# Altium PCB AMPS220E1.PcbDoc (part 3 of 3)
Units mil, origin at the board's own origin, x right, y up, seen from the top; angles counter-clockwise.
Board outline 4800 x 2800 mil, 4 copper layers (Top Layer, GND_Split, GROUND, Bottom Layer), stack 62.6 mil thick; 263 components, 127 nets, 663 pads, 225 vias.
Unrouted connection lines stored in the file: 38.
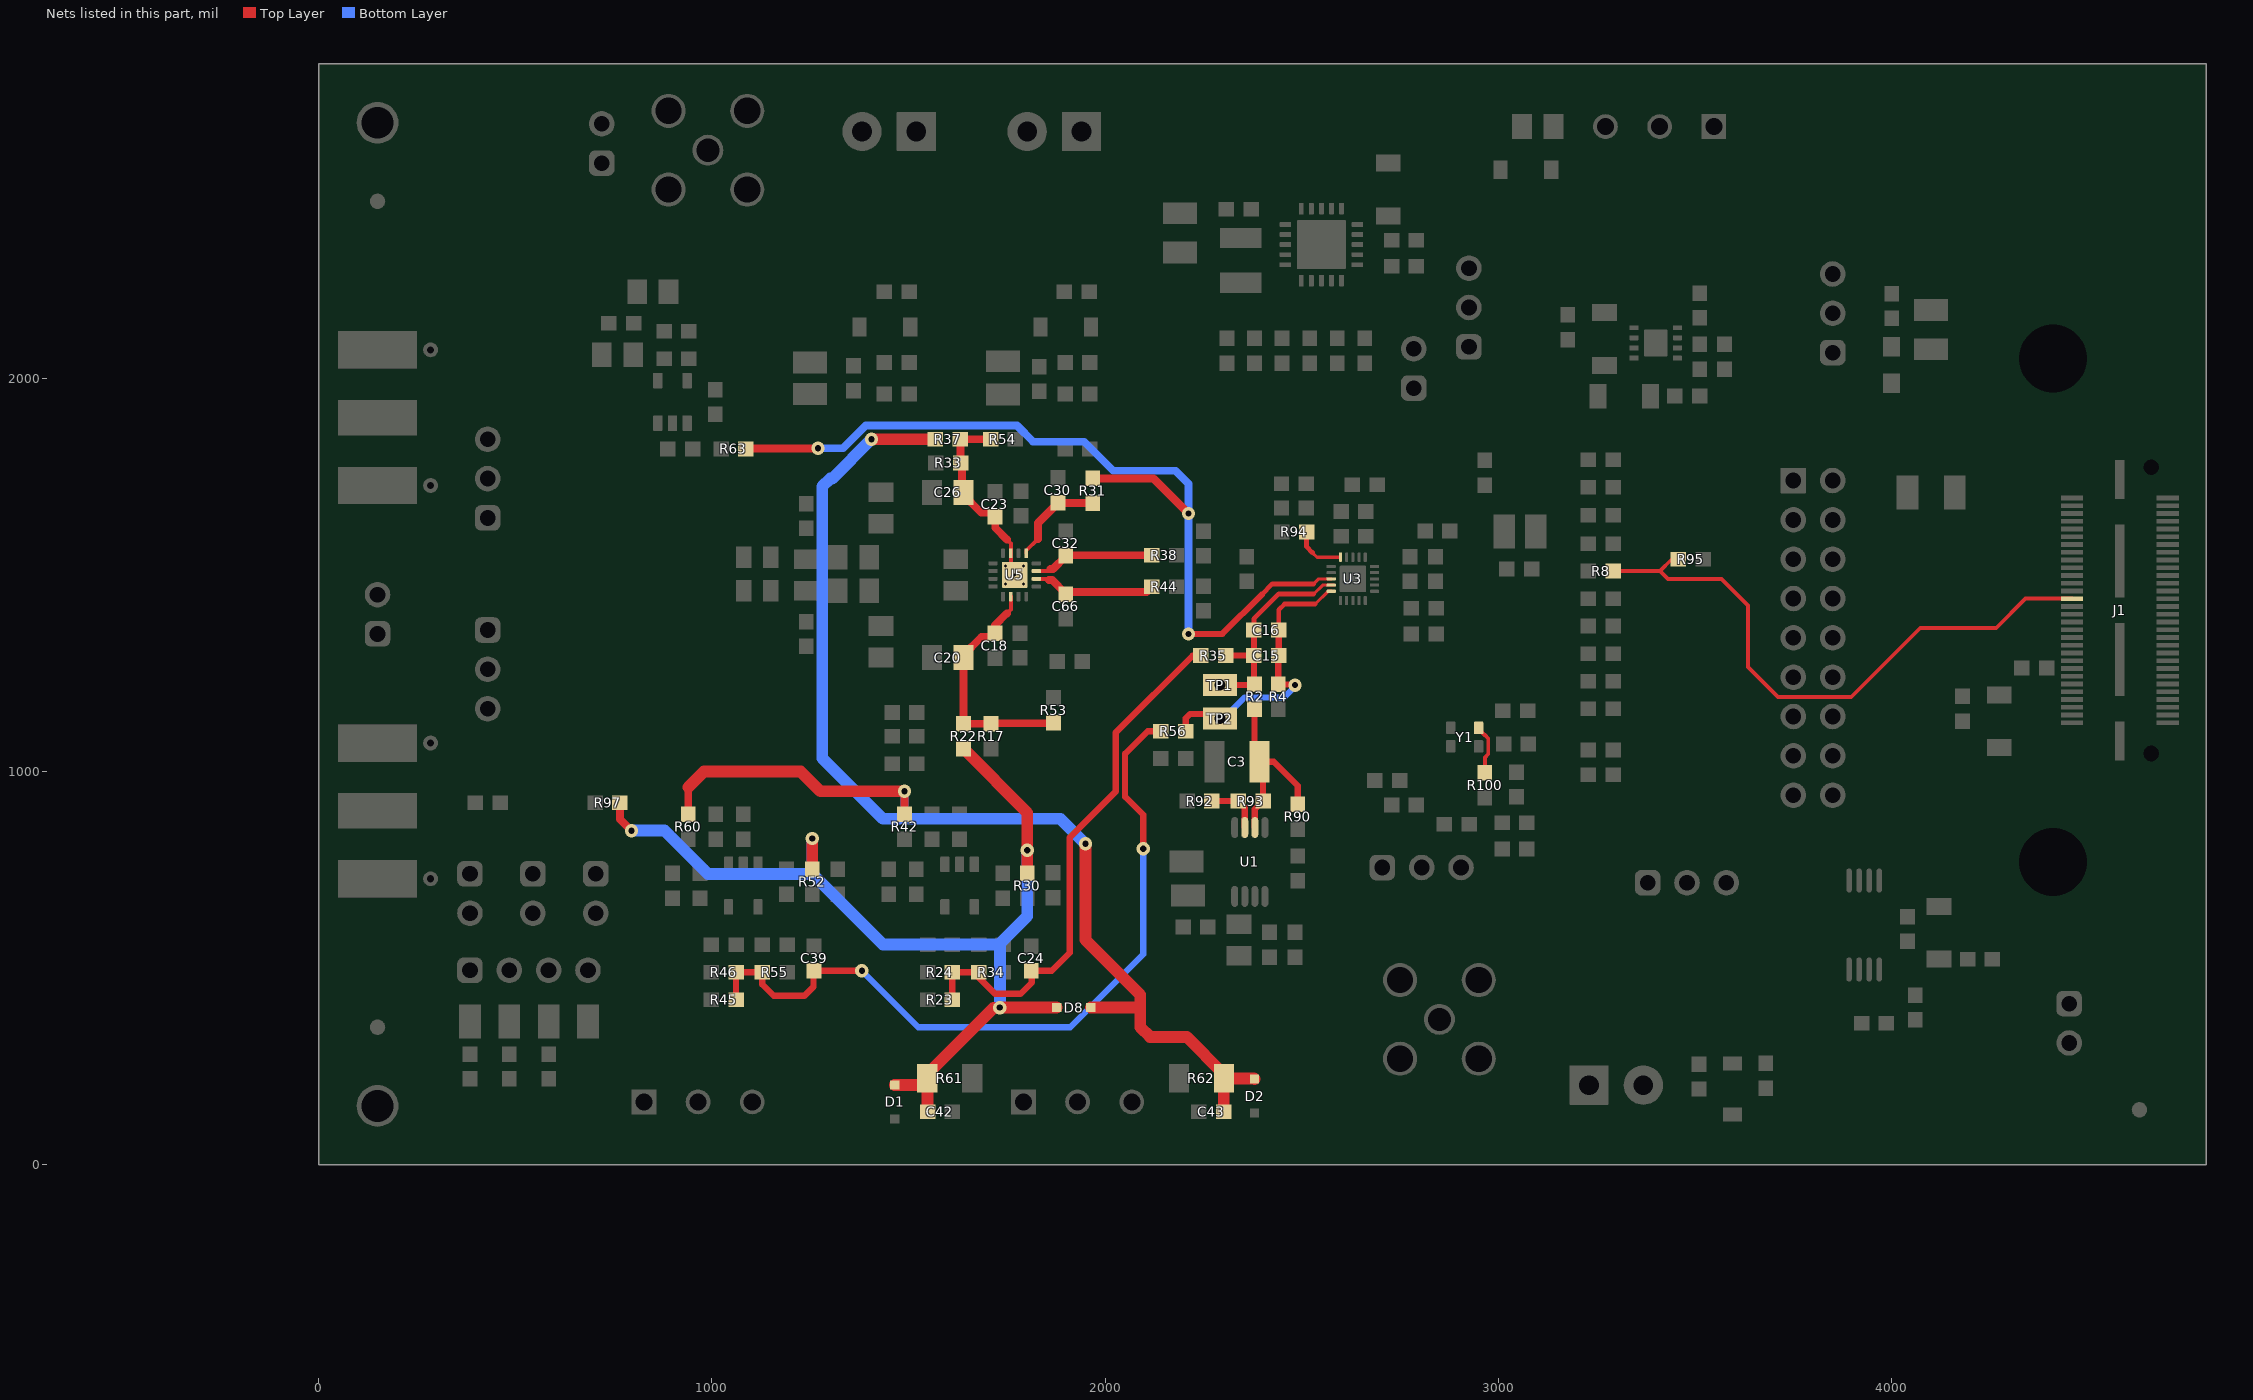
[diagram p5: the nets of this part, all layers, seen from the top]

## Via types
v1: diameter 34, hole 16, Top Layer to Bottom Layer, tented both sides, 161 vias
v2: diameter 34, hole 16, Top Layer to Bottom Layer, 30 vias
v3: diameter 50, hole 28, Top Layer to Bottom Layer, 15 vias
v4: diameter 19.68, hole 7.87, Top Layer to Bottom Layer, tented both sides, 10 vias
v5: diameter 19.68, hole 7.87, Top Layer to Bottom Layer, 9 vias

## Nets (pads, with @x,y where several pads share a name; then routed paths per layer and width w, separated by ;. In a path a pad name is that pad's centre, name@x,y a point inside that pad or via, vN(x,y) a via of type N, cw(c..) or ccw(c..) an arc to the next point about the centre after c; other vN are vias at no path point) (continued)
NetR92_2: R92.2 R93.1 U1.7 | length 141.1
  Top Layer w16: R92.2@2271.5,925 R93.1@2338.5,924.98 2355.16,908.33 U1.7@2355.16,857.84
NetR94_2: R94.2 U3.20 | length 135
  Top Layer w8: 2527.05,1556.92 2538.7,1545.27 2538.7,1545.12 U3.20@2598.5,1545.12
  Top Layer w12: R94.2@2512.16,1609.33 2512.16,1571.81 2527.05,1556.92
NetR100_2: R100.2 Y1.3 | length 128.7
  Top Layer w10: Y1.3@2949.71,1111.31 2949.71,1107.37 2964.57,1092.51 2965.61,1092.51 2974.22,1083.9 2974.22,1044.23 2965.65,1035.66 R100.2@2965.65,996.89
OUTN: C32.1 R38.1 U5.11 | length 310.6
  Top Layer w10: U5.11@1825.12,1509.84 1856.13,1509.84 1861.21,1514.92
  Top Layer w20: 1861.21,1514.92 1867.4,1514.92 1900,1547.52 C32.1@1900,1548.5 1901.5,1550 R38.1@2118.5,1550
OUTP: C66.1 R44.1 U5.10 | length 316.3
  Top Layer w10: U5.10@1825.12,1490.16 1857.65,1490.16
  Top Layer w20: 1857.65,1486.97 1865.51,1486.97 1900,1452.48 C66.1@1900,1451.5 1905,1456.5 2105,1456.5 R44.1@2118.5,1470
REFN: C15.1 C16.2 R4.2 R56.2 TP2.1 U3.5 | length 773.1
  Top Layer w8: 2513.86,1426.02 2534.65,1426.02 2567.13,1458.5 U3.5@2574.88,1458.5
  Top Layer w12: C15.1@2440,1288.5 C15.1@2441.5,1295 ; C16.2@2441.5,1360 2441.5,1411.4 2456.12,1426.02 2534.65,1426.02
  Top Layer w16: R56.2@2205.04,1102.43 2205.04,1135.38 2216.31,1146.65 2280.1,1146.65 v3(2291.74,1135) TP2.1@2286.04,1129.3 ; C15.1@2440,1288.5 R4.2@2440,1221.5 2481.46,1221.5 v1(2482.95,1220) ; C15.1@2441.5,1295 C16.2@2441.5,1360
  Bottom Layer w16: v3(2291.74,1135) 2301.44,1135 2355,1188.56 2454.16,1188.56 2454.46,1188.25 2482.95,1216.74 v1(2482.95,1220)
REFNb: C39.1 R45.1 R46.1 R55.2 R56.1 | length 1977.8
  Top Layer w16: R45.1@1061.5,420 R46.1@1061.5,490 R55.2@1128.5,490 1128.5,458.86 1157.36,430 1235.59,430 1258.5,452.91 1258.5,492.01 C39.1@1260,493.5 v1(1381.65,493.5) ; v1(2097.05,803.5) 2097.05,890.04 2050.74,936.35 2050.74,1045.12 2108.05,1102.43 R56.1@2142.05,1102.43
  Bottom Layer w16: v1(1381.65,493.5) 1525.16,350 1911.33,350 2097.05,535.72 v1(2097.05,803.5)
REFP: C15.2 C16.1 R2.2 R35.2 TP1.1 U3.4 | length 581.4
  Top Layer w8: 2513.86,1451.61 2530.37,1451.61 2553,1474.25 U3.4@2574.88,1474.25 2581.41,1474.25 U3.4@2581.47,1474.32
  Top Layer w12: C16.1@2378.5,1360 2378.5,1388.5 2441.61,1451.61 2530.37,1451.61
  Top Layer w16: v3(2291.74,1220) 2378.5,1220 R2.2@2380,1221.5 ; R35.2@2306.58,1295 C15.2@2378.5,1295 ; R2.2@2378.5,1222.99 C15.2@2378.5,1295 ; C16.1@2378.5,1360 C15.2@2378.5,1295
REFPb: C24.1 R23.1 R24.1 R34.2 R35.1 | length 1366.2
  Top Layer w16: R23.1@1611.5,420 R24.1@1611.5,490 R34.2@1678.5,490 1678.5,476.5 1720,435 1785,435 1813.62,463.62 1813.62,493.5 1864.34,493.5 1910,539.17 1910,832.5 2026.87,949.37 2026.87,1099.37 2222.5,1295 R35.1@2243.58,1295
RET_SCLK: J1.28 R8.2 R95.1 | length 1553.8
  Top Layer w10: R8.2@3291.5,1510 3410.74,1510 ; R95.1@3457.85,1540 3440.74,1540 3410.74,1510 ; J1.28@4458.5,1439.6 4339.91,1439.6 4265.8,1365.49 4072.65,1365.49 3897.16,1190 3710.89,1190 3635,1265.89 3635,1421.84 3566.84,1490 3430.74,1490 3410.74,1510
VCM: R31.1 R63.2 U3.3 | length 2311.2
  Top Layer w8: 2513.86,1477.2 2530.37,1477.2 2543.16,1490 U3.3@2574.88,1490
  Top Layer w12: 2398.01,1450 2425.21,1477.2 2530.37,1477.2
  Top Layer w16: v2(2211.97,1350) 2298.01,1350 2398.01,1450
  Top Layer w20: R63.2@1086.5,1820.31 1087.48,1821.29 1269.02,1821.29 v2(1270,1822.27) ; R31.1@1968.35,1745.34 2123.04,1745.34 v2(2212,1656.38)
  Bottom Layer w20: v2(1270,1822.27) 1333.79,1822.27 1391.4,1879.87 1775.81,1879.87 1816.98,1838.7 1946.98,1838.7 2020.67,1765.01 2178.82,1765.01 2212,1731.83 v2(2212,1656.38) ; v2(2211.97,1350) v2(2212,1656.38)
VM: C43.2 D2.2 D8.2 R37.2 R42.2 R60.2 R62.2 | length 3662.1
  Top Layer w20: R60.2@940,891.5 940,960 ; R42.2@1490,891.5 v1(1490,950)
  Top Layer w30: 940,960 980,1000 1225.98,1000 1275.98,950 v1(1490,950) ; v2(1405.84,1845) R37.2@1568.66,1845 ; v1(1950,816.24) 1950,572.32 2089.48,432.84 2089.48,391.51 ; D8.2@1963.31,400 2080.98,400 2089.48,391.51 ; C43.2@2301.5,135 2301.79,135.3 2301.79,219.7 R62.2@2302.09,220 ; D2.2@2380,218.31 2378.31,220 R62.2@2302.09,220 ; 2089.48,391.51 2089.48,350.17 2114.28,325.37 2207.54,325.37 2302.09,230.83 R62.2@2302.09,220
  Bottom Layer w20: 1490,880 v1(1490,950)
  Bottom Layer w30: v2(1405.84,1845) 1305.84,1745 1301,1745 1281,1725 1281,1034 1435,880 1490,880 1886.24,880 v1(1950,816.24)
VMAMP: C23.1 C26.1 R33.1 R37.1 R54.2 U5.15 U5.17 | length 792.5
  Top Layer w10: 1750.2,1590.37 1760.16,1580.41 1760.16,1509.84 v4(1770,1500)
  Top Layer w20: R37.1@1631.65,1845 R54.2@1708.73,1845 ; R37.1@1632.14,1844.51 1632.14,1785.2 R33.1@1632.63,1784.71 1636.31,1781.03 1636.31,1707.19 1685.31,1658.19 C23.1@1711.3,1658.19 ; C23.1@1720,1648.5 1720.55,1647.96 1720.55,1620.02 1750.2,1590.37
  Bottom Layer w12: v4(1747.17,1477.17) v4(1792.83,1477.17) ; v4(1747.17,1477.17) v4(1747.17,1522.83) ; v4(1747.17,1477.17) v4(1770,1500) ; v4(1747.17,1522.83) v4(1792.83,1522.83) ; v4(1747.17,1522.83) v4(1770,1500) ; v4(1770,1500) v4(1792.83,1522.83) ; v4(1770,1500) v4(1792.83,1477.17) ; v4(1792.83,1477.17) v4(1792.83,1522.83)
VOCM: C30.1 R31.2 U5.13 | length 250.3
  Top Layer w10: U5.13@1799.53,1555.12 1799.53,1561.85 1829.2,1591.52
  Top Layer w20: 1829.2,1591.52 1829.2,1632.22 C30.1@1880,1683.02 ; C30.1@1880,1684 1880.83,1683.18 1967.52,1683.18 R31.2@1968.35,1682.35
VP: C42.2 D1.1 D8.1 R22.2 R30.2 R52.2 R61.1 R97.1 | length 2655.7
  Top Layer w20: R97.1@766.5,920.71 766.5,878.75 v2(795.75,849.49)
  Top Layer w30: R52.2@1255.59,751.5 v1(1255.59,830) ; D1.1@1465,203.31 R61.1@1537.32,203.31 ; R61.1@1547.91,220 1547.91,230.83 v1@1716.32,399.23 ; R61.1@1548.21,203.31 1548.21,135.3 C42.2@1548.5,135 ; R22.2@1640,1058.5 1640,1057.52 1802,895.52 v1(1802,800) R30.2@1802,741.5 ; v1(1732.41,400) D8.1@1876.69,400
  Bottom Layer w30: v2@795.24,850 880,850 990,740 1255.59,740 ; v1(1255.59,830) 1255.59,740 ; v1(1732.41,400) 1732.41,557.59 1730,560 ; v1(1802,800) 1802,632 1730,560 ; 1255.59,740 1435.59,560 1730,560
VPAMP: C18.1 C20.1 R17.1 R22.1 R53.1 U5.6 | length 605.3
  Top Layer w10: 1750.23,1402.4 1760.16,1412.33 U5.6@1760.16,1444.88
  Top Layer w20: C18.1@1711.3,1341.81 1685.31,1341.81 1640,1296.5 R22.1@1640,1121.5 R17.1@1710,1121.5 1711.5,1123 1867.47,1123 R53.1@1868.98,1124.5 ; C18.1@1720,1351.5 1720.03,1372.24 1750.2,1402.4
VREF_2v5: C3.1 R2.1 R90.2 R93.2 U1.6 | length 488.9
  Top Layer w16: R2.1@2380,1158.5 2380,1037.09 C3.1@2392.09,1025 ; U1.6@2380.75,857.84 2380.75,904.24 R93.2@2401.5,924.98 2401.5,1015.59 C3.1@2392.09,1025 ; R90.2@2490,916.5 2490,964 2429,1025 C3.1@2392.09,1025
pads on no net: FID1.1 FID2.1 FID3.1 H4.0 H5.0 H6.0 H7.0 H8. H9. J1.4 J1.5 J1.7 J1.9 J1.11 J1.13 J1.14 J1.15 J1.17 J1.19 J1.20 J1.21 J1.23 J1.25 J1.27 J1.29 J1.31 J1.33 J1.35 J1.37 J1.39 J1.40 J1.41 J1.42 J1.43 J1.44 J1.45 J1.46 J1.47 J1.48 J1.49 J1.51 J1.52 J1.53 J1.54 J1.55 J1.57 J1.MH1 J1.MH2 LBL1.0 SH-J1.0 SH-J2.0 SH-J3.0 SH-J4.0 SH-J5.0 SH-J6.0 SH-J7.0 SH-J8.0 SH-J9.0 U5.8 U8.2 U8.4 U8.5 U8.17 U8.18 U8.19 U8.21@2519.09,2309.09 U8.21@2519.09,2370.91 U8.21@2580.91,2309.09 U8.21@2580.91,2370.91 U9.3 U9.7
copper on no net:
  other v1: 2670.63,862.61

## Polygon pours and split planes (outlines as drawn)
GND on Top Layer "TOP_LAYER_GND_P056" (solid, remove dead copper, pour order 56): 4720,1845 4720,0 2600,0 2600,1225 2850,1225 2850,1845
AVSS on Top Layer "TOP_LAYER_AVSS_P014" (solid, remove dead copper, pour order 14): 2985,2241.49 2982.38,2238.86 2830,2238.86 2830,2750 1200,2750 1200,2290 1475,2290 1475,2015 1482.99,2007.01 1680,2007.01 1680,2305.86 1940,2305.86 1940,2007.01 2134.69,2007.01 2134.69,1775.37 2400,1775.37 2400,1590 2791.5,1590 2791.5,1705 2791.5,1898.5 2985,1898.5
GND on Top Layer "TOP_LAYER_GND_P023" (solid, remove dead copper, pour order 23): 2385,0 2385,275 2385,0 2547,0 2547,300 300,300 300,2380 1160,2380 1160,2750 0,2750 0,0
AVSS on Top Layer "TOP_LAYER_AVSS_P049" (solid, remove dead copper, pour order 49): 2551.75,1180 2551.75,470 2060,470 2060,1180
GND on Top Layer "TOP_LAYER_GND_P047" (solid, remove dead copper, pour order 47): 4199.46,1875 4199.46,1830 4639.99,1830 4639.99,2153.58 4513.67,2279.9 4513.67,2280.79 3639.46,2280.79 3639.46,2714.8 3275,2714.8 3275,1875
EVM_REG_5V5 on Top Layer "TOP_LAYER_EVM_REG_5V5_P043" (solid, remove dead copper, pour order 43): 3790,2129.96 3910,2130.08 3910,2287.72 4032.28,2410 4730,2410 4730,1690 4670,1690 4670,2160.77 4537.8,2292.97 4200.68,2292.97 4200.68,2020 3790,2020
AVDD1 on Top Layer "TOP_LAYER_AVDD1_P033" (solid, remove dead copper, pour order 33): 1458.5,2175 1330.2,2175 1330.2,2085 1331.7,2083.5 1458.5,2083.5 1458.5,1928.5 1400,1928.5 1400,2009.3 1180.7,2009.3 1180,2010 1180,2238.5 1458.5,2238.5
EVM_ID_PWR on Top Layer "TOP_LAYER_EVM_ID_PWR_P020" (solid, remove dead copper, pour order 20): 4030,464.47 4030,414.47 4213.88,414.47 4213.88,590 3961.02,590 3961.02,464.47
NetJ1_59 on Top Layer "TOP_LAYER_NETJ1_59_P012" (solid, remove dead copper, pour order 12): 4680,1134.35 4680,659.67 4570,549.67 4250,549.67 4250,496.48 4626.81,496.48 4730,599.67 4730,1134.35
5V_LDO on Top Layer "TOP_LAYER_5V_LDO_P010" (solid, remove dead copper, pour order 10): 2110,2330 2110,2516.65 2505,2516.65 2505,2455.66 2505,2330 2345,2330 2345,2460.66 2345,2330
NetC48_2 on Top Layer "TOP_LAYER_NETC48_2_P002" (solid, remove dead copper, pour order 2): 2595,2464.92 2595,2385 2830,2385 2830,2464.92
GND on Bottom Layer "BOTTOM_LAYER_GND_P045" (solid, remove dead copper, pour order 45): 2620,1350 2810,1350 2810,1865 4720,1865 4720,20 2620,20
VMAMP on Bottom Layer "BOTTOM_LAYER_VMAMP_P055" (solid, remove dead copper, pour order 55): 1370,1900 2170,1900 2170,1100 1370,1100
GND on Bottom Layer "BOTTOM_LAYER_GND_P051" (solid, remove dead copper, pour order 51): 2865.37,2750 4300,2750 4720,2330 4720,1820 4200,1820 4200,1890 2865.38,1890
GND on GROUND (split plane): 4779.9,20.1 2610.05,20.1 2608.6,1417.66 2661.73,1418.89 2662.13,1418.95 2662.53,1418.94 2663.42,1419.16 2664.33,1419.3 2664.7,1419.46 2665.09,1419.55 2665.9,1419.99 2666.74,1420.36 2667.05,1420.61 2667.41,1420.8 2696.93,1442.16 2697.52,1442.71 2698.16,1443.2 2698.47,1443.61 2698.85,1443.97 2699.27,1444.65 2699.76,1445.29 2699.96,1445.77 2700.23,1446.21 2700.46,1446.98 2700.77,1447.72 2700.83,1448.24 2700.98,1448.74 2701.01,1449.54 2701.11,1450.33 2701.11,1542.38 2806.47,1611.16 2807.26,1611.84 2808.09,1612.47 2808.26,1612.69 2808.47,1612.87 2809.05,1613.74 2809.69,1614.56 2809.8,1614.82 2809.95,1615.05 2810.3,1616.03 2810.7,1617 2810.73,1617.27 2810.82,1617.53 2810.9,1618.57 2811.04,1619.61 2811.04,1848.82 4198.37,1848.82 4200.98,1849.17 4203.41,1850.17 4205.5,1851.78 4207.1,1853.86 4208.11,1856.3 4208.46,1858.91 4208.11,1861.52 4207.1,1863.95 4205.5,1866.04 4203.41,1867.64 4200.98,1868.65 4198.37,1868.99 2800.95,1868.99 2798.34,1868.65 2795.91,1867.64 2793.82,1866.04 2792.22,1863.95 2791.21,1861.52 2790.87,1858.91 2790.87,1625.07 2685.51,1556.29 2684.72,1555.61 2683.89,1554.98 2683.72,1554.76 2683.51,1554.57 2682.92,1553.71 2682.29,1552.89 2682.18,1552.63 2682.03,1552.4 2681.68,1551.42 2681.28,1550.45 2681.24,1550.18 2681.15,1549.92 2681.07,1548.88 2680.94,1547.84 2680.94,1455.49 2658.13,1438.99 2603.52,1437.72 2601.1,1438.72 2598.49,1439.06 2595.88,1438.72 2593.45,1437.71 2591.36,1436.1 2589.76,1434.01 2588.76,1431.58 2588.42,1428.97 2589.88,20.1 20.1,20.1 20.1,2779.9 4779.9,2779.9
AVSS on GND_Split (split plane): 2989.91,1910.55 2829.97,1910.09 2828.68,1909.91 2827.39,1909.74 2827.38,1909.74 2827.36,1909.73 2826.17,1909.24 2824.96,1908.74 2824.94,1908.73 2824.93,1908.72 2823.91,1907.93 2822.87,1907.13 2822.86,1907.12 2822.85,1907.11 2822.06,1906.08 2821.26,1905.04 2821.26,1905.03 2821.25,1905.02 2820.75,1903.81 2820.26,1902.61 2820.26,1902.6 2820.25,1902.58 2820.08,1901.28 2819.91,1900 2819.91,1655.1 2686.48,1556.79 2685.98,1556.58 2683.89,1554.98 2682.29,1552.89 2681.28,1550.45 2680.94,1547.84 2680.94,1453.86 2669.14,1439.06 2598.5,1439.06 2597.94,1438.99 2597.37,1439 2596.64,1438.82 2595.89,1438.72 2595.37,1438.5 2594.82,1438.36 2594.16,1438 2593.46,1437.71 2593.01,1437.36 2592.51,1437.09 2591.97,1436.57 2591.37,1436.11 2591.03,1435.66 2590.62,1435.26 2573.6,1413.9 2573.21,1413.26 2572.75,1412.66 2572.53,1412.14 2572.24,1411.65 2572.03,1410.92 2571.74,1410.23 2571.67,1409.66 2571.51,1409.12 2571.5,1408.36 2571.4,1407.62 2571.41,20.1 20.1,20.1 20.1,2779.9 2989.91,2779.9
GND on GND_Split (split plane): 4779.9,20.1 2591.58,20.1 2591.57,1404.09 2603.36,1418.89 2674,1418.89 2674.57,1418.96 2675.14,1418.95 2675.87,1419.14 2676.61,1419.23 2677.14,1419.45 2677.69,1419.59 2678.35,1419.95 2679.05,1420.24 2679.5,1420.59 2680,1420.86 2680.54,1421.39 2681.14,1421.84 2681.48,1422.3 2681.89,1422.69 2698.91,1444.05 2699.3,1444.69 2699.76,1445.29 2699.98,1445.82 2700.27,1446.3 2700.48,1447.03 2700.77,1447.72 2700.84,1448.29 2701,1448.84 2701.01,1449.59 2701.11,1450.33 2701.11,1542.51 2835.98,1641.88 2836.53,1642.41 2837.13,1642.87 2837.47,1643.31 2837.88,1643.7 2838.27,1644.35 2838.74,1644.96 2838.95,1645.48 2839.24,1645.96 2839.45,1646.69 2839.74,1647.39 2839.82,1647.95 2839.97,1648.49 2839.99,1649.25 2840.09,1650 2840.09,1889.94 2997.04,1890.4 2997.39,1890.26 3000,1889.91 3002.61,1890.26 3003,1890.42 4200.03,1893.91 4202.64,1894.27 4205.07,1895.28 4207.15,1896.89 4208.75,1898.98 4209.75,1901.42 4210.09,1904.03 4209.73,1906.64 4208.72,1909.07 4207.11,1911.15 4205.02,1912.75 4202.58,1913.75 4199.97,1914.09 3010.09,1910.61 3010.09,2779.9 4779.9,2779.9

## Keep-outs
Keep-Out Layer:
  text ".Layer_Name" at 577,-858.49 h60

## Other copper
Top Layer:
  pour cut-out: 3810,1580 3810,1064.63 3834.63,1040 3900.61,1040 4080,1219.39 4080,1560 3940,1560 3920,1580
  pour cut-out: 2700,2380 2830,2380 2830,2250 2700,2250
  pour cut-out: 4550,1780 4610,1780 4610,1040 4550,1040
  text ".Layer_Name" at 577,-858.49 h60
Bottom Layer:
  text ".Layer_Name" at 577,-858.49 h60
GND_Split (plane layer: these items are gaps in the copper):
  pour cut-out: 2008.53,1518.06 1800.69,1518.06 1800.69,1639.06 2008.53,1639.06
  pour cut-out: 2011.89,1360 1804.05,1360 1804.05,1481 2011.89,1481
  lines w20: 2581.5,0 2581.48,1407.62 2598.5,1428.98 2674,1428.98 2691.02,1450.33 2691.02,1547.84 ; 2691.35,1547.84 2830,1650 2830,1900 4200,1904 ; 3000,1900 3000,2800 ; 3204.12,1196.5 3221.14,1217.86
GROUND (plane layer: these items are gaps in the copper):
  pour cut-out: 2008.54,1520.02 1800.7,1520.02 1800.7,1641.02 2008.54,1641.02
  pour cut-out: 2011.89,1358.78 1804.05,1358.78 1804.05,1479.79 2011.89,1479.79
  lines w20: 2300,0 4500,0 ; 2598.5,1427.52 2661.5,1428.98 2691.02,1450.33 2691.02,1547.84 2800.95,1619.61 2800.95,1858.91 4198.37,1858.91 ; 2598.5,1428.98 2600,-10

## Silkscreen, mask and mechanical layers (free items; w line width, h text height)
Top Overlay:
  lines w7: 2875,2324.12 2875,2020 2975,2020 2975,2324.12 ; 3530,1180 3680,1180 ; 3571.7,1774 3671.7,1774 ; 3610,1470 3680,1470 ; 3920,890 3950,890 3950,1790 3920,1790 ; 3950,1340 3975,1340 ; 100,1250 100,1550 200,1550 200,1250 100,1250 ; 2654.39,710.75 2654.39,810.75 2954.39,810.75 2954.39,710.75 2654.39,710.75 ; 3330.25,669.29 3330.25,769.29 3630.25,769.29 3630.25,669.29 3330.25,669.29
  lines w8: 2875,2324.12 2975,2324.12
  lines w10: 574.54,1576.35 1010.54,1578.35 ; 804.54,1575.35 807.49,1086.82
  lines w12: 4000.09,2550 4000.09,2550.09
  lines w20: 3965,1923.66 4035.43,1923.66
  text "VCM" at 540,2633.84 h40
  text "GND" at 540,2530 h40
  text "PGA85x-ADS127L2EVM" at 4093.43,2466.28 h30
  text "AVDD1" at 1225,2425 h40
  text "GND" at 1475,2425 h40
  text "AVDD2" at 1650,2425 h40
  text "GND" at 1893.89,2425 h40
  text "VCOM Out" at 850,2360 h40
  text "+Vin" at 3671.7,2281.5 h30
  text "-2.5V" at 2990,2260 h30
  text "-Vin" at 3150,2240 h40
  text "Gnd" at 3305,2240 h40
  text "+Vin" at 3465,2240 h40
  text "AINN" at 174.28,2160.01 h40
  text "AVSS" at 2990,2157.91 h30
  text "+LDO / Vin" at 3635,2129.98 h30
  text "Gnd" at 2990,2055 h30
  text "+5.5V / EVM" at 3620,2000 h30
  text "LDO DISABLE" at 2775.34,1795.85 h40
  text "RST" at 3571.7,1720 h40
  text "START" at 3490,1620 h40
  text "A2" at 558.49,1606.37 h40
  text "Gain" at 843.61,1605.35 h40
  text "A1" at 647.04,1604.35 h40
  text "A0" at 730.88,1603.82 h40
  text "0" at 577.49,1529.65 h40
  text "0" at 662.51,1529.65 h40
  text "0" at 750.96,1529.65 h40
  text "0.125 V/V" at 843.62,1529.48 h40
  text "SDI" at 3580,1510 h40
  text "0" at 577.49,1466.82 h40
  text "0" at 662.51,1466.82 h40
  text "1" at 750.96,1466.6 h40
  text "0.25 V/V" at 843.62,1466.66 h40
  text "AINN" at 219.21,1434.29 h40
  text "0" at 577.49,1410.31 h40
  text "1" at 662.51,1410.09 h40
  text "0" at 750.96,1410.31 h40
  text "0.5 V/V" at 843.62,1410.14 h40
  text "CS" at 3610,1410 h40
  text "0" at 577.49,1347.71 h40
  text "1 V/V" at 843.62,1347.54 h40
  text "1" at 662.51,1347.48 h40
  text "1" at 750.96,1347.48 h40
  text "AINP" at 219.51,1333.76 h40
  text "SCLK" at 3530,1330 h40
  text "GND" at 3990,1320 h40
  text "1" at 579.49,1283.65 h40
  text "0" at 664.51,1283.65 h40
  text "0" at 752.96,1283.65 h40
  text "2V/V" at 845.62,1283.48 h40
  text "1" at 579.49,1220.82 h40
  text "0" at 664.51,1220.82 h40
  text "1" at 752.96,1220.6 h40
  text "4 V/V" at 845.62,1220.66 h40
  text "SDO" at 3570,1220 h40
  text "1" at 579.49,1164.31 h40
  text "1" at 664.51,1164.09 h40
  text "0" at 752.96,1164.31 h40
  text "8 V/V" at 845.62,1164.14 h40
  text "AINP" at 207.31,1160 h40
  text "DRDY" at 3535,1120 h40
  text "1" at 579.49,1101.71 h40
  text "16 V/V" at 845.62,1101.54 h40
  text "1" at 664.51,1101.48 h40
  text "1" at 752.96,1101.48 h40
  text "MCLKi" at 3500,1015 h40
  text "MCLKo" at 3495,920 h40
  text "OSC / SHTDN" at 3630,705 h40
  text "CLOCK SELECT" at 3034.61,633.54 h40
  text "EXT / Clk" at 2599.36,606.94 h30
  text "EVM / Clk" at 2807.36,597.34 h30
  text "PHI / Clk" at 3476.5,559.81 h30
  text "EVM/EXT / Clk" at 3270,537.65 h30
  text "EXT CLOCK" at 2681.61,530 h40
  text "Amp Supply" at 2000,369.5 h40
  text "IOVDD" at 3354.63,341.65 h40
  text "GND" at 3171.1,338.98 h40
  text "REFN" at 730,330 h40
  text "GND" at 911.5,330 h40
  text "REFP" at 1050,330 h40
  text "VM" at 2036.77,325.13 h40
  text "VP" at 1681.46,282.63 h40
  text "GND" at 1641.18,235.04 h40
  text ".Layer_Name" at 577,-858.49 h60
Bottom Overlay:
  text "'.PRJ_Number'.PCB_Rev" at 1083.5,1768.83 h108.27
  text ".Layer_Name" at 577,-858.49 h60
Top Paste:
  text ".Layer_Name" at 577,-858.49 h60
Bottom Paste:
  text ".Layer_Name" at 577,-858.49 h60
Top Solder:
  text ".Layer_Name" at 577,-858.49 h60
  text ".Layer_Name" at 577,-858.49 h60
Bottom Solder:
  text ".Layer_Name" at 577,-858.49 h60
Drill Guide:
  text ".Layer_Name" at 577,-858.49 h60
M1 Board Outline:
  the board outline again, w10
  text ".Layer_Name" at 577,-858.49 h60
M2 Board Dimensions:
  rectangle: 0,-275 125,-150
  rectangle: 125,-400 500,-275
  lines w7: 0,-275 1000,-275 ; 125,-400 125,-150 ; 250,-400 250,-150 ; 500,-400 500,-150 ; 750,-400 750,-150 ; 0,-400 1000,-400 1000,-150 0,-150 0,-400
  text ".Layer_Name" at 577,-858.49 h60
M3 3D STEP Top:
  text ".Layer_Name" at 577,-858.49 h60
M4 3D STEP Bottom:
  text ".Layer_Name" at 577,-858.49 h60
M5 Assembly Top:
  lines w10: -292,-930.17 6308,-930.17 ; -292,-726.83 6310,-726.83 ; -292,-523.5 -292,-1133.5 3713,-1133.5 6310,-1133.5 6310,-523.5 -291.5,-523.5 -291.5,-1133.5 1284,-1133.5 ; 2173,-1133.5 2173,-523.5 ; 3440,-726.83 3440,-523.5 ; 4280,-726.83 4280,-523.5 ; 4902,-1140 4902,-937.17
  text "COMPONENTS MARKED 'DNP' SHOULD NOT BE POPULATED." at 1153.5,-318.5 h60
  text "ASSEMBLY VARIANT:" at 1153,-434 h60
  text ".VariantName" at 2189,-434 h60
  text "PCB VIEWED FROM TOP SIDE" at -228.5,-655.67 h60
  text "BOARD #:" at 2248,-655.67 h60
  text ".PRJ_Number" at 2793.5,-655.67 h60
  text "REV:" at 3638,-655.67 h60
  text ".PCB_Rev" at 3929.5,-655.67 h60
  text "SVN REV:" at 4476,-655.67 h60
  text ".VersionControl_RevNumber" at 4982,-655.67 h60
  text "TID #:" at 2248,-859 h60
  text ".TID" at 2793.5,-859 h60
  text "PLOT NAME =" at -228.5,-1064.34 h60
  text ".plot_File_Name" at 577,-1064.34 h60
  text "GENERATED    :" at 2250,-1064.34 h60
  text ".Print_Date" at 3119.5,-1064.34 h60
  text ".Print_Time" at 3848.5,-1064.34 h60
  text "TEXAS INSTRUMENTS" at 5113,-1064.34 h60
M6 Assembly Bottom:
  lines w10: -292.5,-727.33 6309.5,-727.33 ; -290.5,-930.67 6309.5,-930.67 ; 1115.5,-1140.5 1115.5,-937.67 ; 1737.5,-727.33 1737.5,-524 ; 2577.5,-727.33 2577.5,-524 ; 3844.5,-1134 3844.5,-524 ; 4733.5,-1134 6309,-1134 6309,-524 -292.5,-524 -292.5,-1134 2304.5,-1134 6309.5,-1134 6309.5,-524
  text "COMPONENTS MARKED 'DNP' SHOULD NOT BE POPULATED." at 7106,-299 h60
  text ".VariantName" at 5058,-434 h60
  text "ASSEMBLY VARIANT:" at 6981,-456 h60
  text ".VersionControl_RevNumber" at 1035.5,-656.17 h60
  text "SVN REV:" at 1541.5,-656.17 h60
  text ".PCB_Rev" at 2088,-656.17 h60
  text "REV:" at 2379.5,-656.17 h60
  text ".PRJ_Number" at 3224,-656.17 h60
  text "BOARD #:" at 3769.5,-656.17 h60
  text "PCB VIEWED FROM BOTTOM SIDE" at 6246,-656.17 h60
  text ".TID" at 3224,-859.5 h60
  text "TID #:" at 3769.5,-859.5 h60
  text "TEXAS INSTRUMENTS" at 904.5,-1064.84 h60
  text ".Print_Time" at 2169,-1064.84 h60
  text ".Print_Date" at 2898,-1064.84 h60
  text "GENERATED    :" at 3767.5,-1064.84 h60
  text ".plot_File_Name" at 5440.5,-1064.84 h60
  text "PLOT NAME =" at 6246,-1064.84 h60
M9 Title Sheet:
  drawing of 57 lines, arcs and shapes, not listed
  text "1" at 739.84,8036.5 h70
  text "2" at 3235.5,8036.5 h70
  text "3" at 5724.84,8036.5 h70
  text "4" at 8231.51,8036.5 h70
  text "5" at 10730.5,8036.5 h70
  text "6" at 13235.5,8036.5 h70
  text "A" at -416.5,6893.5 h70
  text "A" at 14383.5,6893.5 h70
  text "B" at -416.5,4513.5 h70
  text "B" at 14383.5,4513.5 h70
  text "C" at -416.5,2138.5 h70
  text "C" at 14383.5,2138.5 h70
  text "PROJECT TITLE:" at 11343.5,277.5 h45
  text ".PRJ_Title" at 11393.5,144.17 h70
  text "DESIGNED FOR:" at 11343.5,-23.5 h45
  text ".PRJ_Customer" at 11393.5,-163.5 h70
  text "D" at -416.5,-231.5 h70
  text "D" at 14383.5,-231.5 h70
  text "FILE NAME:" at 11343.5,-323.5 h45
  text ".PCB_File_Name_No_Path" at 11393.5,-443.5 h70
  text "Texas Instruments (TI) and/or its licensors do not warrant the accuracy or completeness of this specification" at 6374,-605.34 h45
  text "ENGINEER:" at 11343.5,-613.5 h45
  text "LAYOUT BY:" at 12848.5,-613.5 h45
  text "or any information contained therein. TI and/or its licensors do not warrant that this design will meet" at 6329.01,-718 h45
  text ".PRJ_Engineer" at 11393.5,-768.49 h70
  text ".PCB_Layout" at 12899,-768.49 h70
  text "the specifications, will be suitable for your application or fit for any particular purpose, or will operate in" at 6329.01,-830.67 h45
  text ".Layer_Name" at 577,-858.49 h60
  text "ALTIUM DESIGNER VERSION:" at 12848.5,-923.5 h45
  text "an implementation. TI and/or its licensors do not warrant that the design is production worthy. You should" at 6329.01,-943.33 h45
  text "completely validate and test your design implementation to confirm the system functionality for your application." at 6374,-1056 h45
  text ".print_Scale" at 11393.5,-1056.83 h70
  text ".Application_BuildNumber" at 12899,-1056.83 h70
  text "1" at 739.84,-1263.5 h70
  text "2" at 3235.5,-1263.5 h70
  text "3" at 5724.84,-1263.5 h70
  text "4" at 8231.51,-1263.5 h70
  text "5" at 10730.5,-1263.5 h70
  text "6" at 13235.5,-1263.5 h70
M10 Fab Notes:
  drawing of 189 lines, arcs and shapes, not listed
  text "DESIGN INFORMATION" at 12382.02,6356.17 h60
  text "MIN. TRACK WIDTH:" at 11737.46,6224.05 h60
  text "8" at 12833.7,6224.05 h60
  text "MIL" at 12988.46,6224.05 h60
  text "MIN. CLEARANCE:" at 11737.46,6099.92 h60
  text "0.2" at 12773.7,6099.93 h60
  text "mm" at 12988.46,6099.92 h60
  text "MIN. VIA PAD SIZE:" at 11737.46,5975.8 h60
  text "24" at 12803.71,5975.8 h60
  text "MIL" at 12988.46,5975.8 h60
  text "0.05mm (2MIL)" at 12432.46,5845.9 h60
  text "MINIMUM ANNULAR RING" at 11408.23,5837.67 h60
  text "EXTERNAL" at 13140.46,5837.67 h60
  text "PER" at 11608.23,5727.55 h60
  text "IPC-D-275 CLASS 2 LEVEL C" at 11828.23,5727.54 h60
  text "MIL, HOLES" at 13316.46,5627.07 h60
  text "+/-" at 12924,5618.48 h60
  text "+/-" at 13778,5618.48 h60
  text "REGISTRATION TOLERANCES:" at 11408.23,5617.42 h60
  text "METAL" at 12608,5617.42 h60
  text "5" at 13184.2,5617.42 h60
  text "3" at 14017.2,5617.42 h60
  text "MIL" at 14133.46,5617.42 h60
  text "HOLE SIZE TOLERANCE (UNLESS OTHERWISE SPECIFIED):" at 11408.23,5519.1 h60
  text "+/-" at 13778,5516.23 h60
  text "3" at 14017.2,5515.17 h60
  text "MIL" at 14133.46,5515.17 h60
  text "MATERIAL:" at 11333.46,5377.52 h60
  text "FR-4 High Tg" at 12319.9,5249 h60
  text "X" at 12175.46,5241.01 h60
  text "FR-408" at 11754.46,5236.49 h60
  text "OTHER" at 13242.46,5236.49 h60
  text "62 MIL (1.6mm) +/-10%" at 12074.56,5093.46 h60
  text "X" at 11954.46,5091.01 h60
  text "THICKNESS:" at 11408.23,5085.24 h60
  text "OTHER" at 13359.46,5085.24 h60
  text "TOLERANCE:" at 11408.23,4946.92 h60
  text "X" at 12256.46,4946.92 h60
  text "ANSI IPC-6012 TYPE 3 CLASS 2" at 12434.48,4946.92 h60
  text "OTHER +/-" at 12434.46,4802.73 h60
  text "BOW & TWIST:" at 11408.23,4657.54 h60
  text "X" at 12256.46,4657.54 h60
  text "ANSI IPC-6012 TYPE 3 CLASS 2" at 12434.48,4657.54 h60
  text "OTHER +/-" at 12434.46,4510.85 h60
  text "DRILLING:" at 11333.46,4380.23 h60
  text "NC_DRILL FILES" at 13094.46,4275.04 h60
  text "REFERENCE:" at 11408.23,4271.1 h60
  text "X" at 12065.46,4271.01 h60
  text "AS SHOWN" at 12243.46,4271.1 h60
  text "X" at 12966.46,4271.1 h60
  text "OTHER" at 13392.46,4128.85 h60
  text "PTH COPPER THICKNESS:" at 11407.91,4125.32 h60
  text "X" at 12547.14,4125.32 h60
  text "20-30 um" at 12675.14,4125.32 h60
  text "BOARD FINISH:" at 11333.46,3977.73 h60
  text "SILKSCREEN:" at 11488.68,3867.6 h60
  text "X" at 12446.46,3867.6 h60
  text "TOP" at 12563.46,3867.6 h60
  text "X" at 12956.46,3867.6 h60
  text "BOTTOM" at 13074.46,3867.6 h60
  text "SILKSCREEN COLOR:" at 11488.68,3712.41 h60
  text "X" at 12445.46,3712.41 h60
  text "WHITE" at 12563.46,3712.41 h60
  text "OTHER" at 13074.46,3712.41 h60
  text "X" at 12576.46,3568.96 h60
  text "GREEN" at 12694.46,3568.96 h60
  text "OTHER" at 13312.46,3568.96 h60
  text "SOLDER RESIST COLOR:" at 11488.68,3562.1 h60
  text "X" at 12576.46,3414.71 h60
  text "MATTE" at 12694.46,3414.71 h60
  text "SEMI-GLOSS" at 13312,3414.07 h60
  text "IMMERSION GOLD (ENIG)" at 12394.46,3241.94 h60
  text "ENEPIG" at 13732,3234.72 h60
  text "SURFACE FINISH:" at 11333.46,3233.72 h60
  text "X" at 12216.46,3233.72 h60
  text "IMM. TIN/SILVER OR EQUIV" at 11663,3096.4 h60
  text "OTHER" at 13094.46,3092.47 h60
  text "ARRAY/PANEL:" at 11333.46,2937.09 h60
  text "CUT AND TRIM PER M1 BOARD OUTLINE" at 12394.46,2928.87 h60
  text "N.C. ROUTE" at 12394.46,2792.9 h60
  text "X" at 13082.46,2792.9 h60
  text "V. SCORE" at 13260.46,2792.9 h60
  text "CERTIFICATION:" at 11333.46,2663.77 h60
  text "MATERIALS AND WORKMANSHIP FOR ALL PCBS" at 12058.46,2663.77 h60
  text "TO MEET OR EXCEED THE REQUIREMENTS OF:" at 12058.46,2569.71 h60
  text "X" at 11695.97,2441.08 h60
  text "ANSI IPC-A-600F CLASS ->" at 11823.96,2441.08 h60
  text "X" at 13471.97,2441.08 h60
  text "2" at 13581.96,2441.08 h60
  text "1" at 13266.96,2439.58 h60
  text "3" at 13935.96,2439.58 h60
  text "X" at 12507.97,2293.39 h60
  text "RoHS" at 12635.96,2293.39 h60
  text "OTHER" at 13280.36,2293.39 h60
  text "PER ORDER" at 13677.42,2293.39 h60
  text "ALL BOARDS MUST MEET OR EXCEED UL94-V0 REQUIREMENTS." at 11361,2139.57 h60
  text "PCB MUST BEAR THE UL94V-0 UL REGISTERED MATERIAL ID NUMBER" at 11361,2023.5 h60
  text "ADDITIONAL REQUIREMENTS:" at 11333.46,1854.08 h60
  text "MICROSECTION:" at 11408.23,1746.95 h60
  text "YES" at 12313.96,1746.95 h60
  text "REQUIRED" at 13175.46,1602.62 h60
  text "BARE BOARD ELEC. TEST:" at 11408.23,1599.76 h60
  text "NONE" at 12713.96,1599.76 h60
  text "X" at 13057.46,1599.76 h60
  text "PER ORDER" at 13767.46,1599.76 h60
  text "XX MIL VIAS REQUIRE NON-CONDUCTIVE FILL AND PLANARIZE" at 11576.38,1394.82 h59
  text "XX MIL VIAS REQUIRE CONDUCTIVE FILL AND PLANARIZE" at 11584.38,1290.84 h60
  text "OUTER XX MIL TRACES REQUIRE 50 OHM SINGLE-ENDED IMPEDANCE" at 11583.39,1127.46 h58
  text "LAYER 2 & 3 (INNER LAYERS) XX MIL WIDE, XX MIL SPACE / TRACES REQUIRE 100 OHM DIFFERENTIAL IMPEDANCE" at 11575.39,891.74 h60
  text ".Layer_Name" at 577,-858.49 h60
M11 Gerber Information:
  lines w10: -292,-930.17 6308,-930.17 ; -292,-726.83 6310,-726.83 ; -292,-523.5 -292,-1133.5 3713,-1133.5 6310,-1133.5 6310,-523.5 -291.5,-523.5 -291.5,-1133.5 1284,-1133.5 ; 2173,-1133.5 2173,-523.5 ; 3440,-726.83 3440,-523.5 ; 4280,-726.83 4280,-523.5 ; 4902,-1140 4902,-937.17
  text "ALL ARTWORK VIEWED FROM TOP SIDE" at -228.5,-655.67 h60
  text "BOARD #:" at 2248,-655.67 h60
  text ".PRJ_Number" at 2793.5,-655.67 h60
  text "REV:" at 3638,-655.67 h60
  text ".PCB_Rev" at 3929.5,-655.67 h60
  text "SVN REV:" at 4476,-655.67 h60
  text ".VersionControl_RevNumber" at 4982,-655.67 h60
  text "LAYER NAME =" at -228.5,-858.49 h60
  text "TID #:" at 2248,-859 h60
  text ".TID" at 2793.5,-859 h60
  text "PLOT NAME =" at -228.5,-1064.34 h60
  text ".plot_File_Name" at 577,-1064.34 h60
  text "GENERATED    :" at 2250,-1064.34 h60
  text ".Print_Date" at 3119.5,-1064.34 h60
  text ".Print_Time" at 3848.5,-1064.34 h60
  text "TEXAS INSTRUMENTS" at 5113,-1064.34 h60
M12 Stackup:
  drawing of 295 lines, arcs and shapes, not listed
  text "Layer" at 6520.74,5797.5 h60
  text "Name" at 6930.65,5797.5 h60
  text "Material" at 7860.4,5797.5 h60
  text "Thickness" at 8720.16,5797.5 h60
  text "Constant" at 9370,5797.5 h60
  text "Board Layer Stack" at 9939.86,5797.5 h60
  text "Top Overlay" at 6930.65,5677.5 h60
  text "Top Solder" at 6930.65,5557.5 h60
  text "Solder Resist" at 7860.4,5557.5 h60
  text "0.40mil" at 8720.16,5557.5 h60
  text "3.5" at 9370,5557.5 h60
  text "1" at 6520.74,5437.5 h60
  text "Top Layer" at 6930.65,5437.5 h60
  text "1.40mil" at 8720.16,5437.5 h60
  text "Dielectric 2" at 6930.65,5317.5 h60
  text "FR-4" at 7860.4,5317.5 h60
  text "9.00mil" at 8720.16,5317.5 h60
  text "4.2" at 9370,5317.5 h60
  text "2" at 6520.74,5197.5 h60
  text "GND_Split" at 6930.65,5197.5 h60
  text "1.40mil" at 8720.16,5197.5 h60
  text "Dielectric1" at 6930.65,5077.5 h60
  text "FR-4" at 7860.4,5077.5 h60
  text "39.00mil" at 8720.16,5077.5 h60
  text "4.2" at 9370,5077.5 h60
  text "3" at 6520.74,4957.5 h60
  text "GROUND" at 6930.65,4957.5 h60
  text "1.40mil" at 8720.16,4957.5 h60
  text "Dielectric 3" at 6930.65,4837.5 h60
  text "FR-4" at 7860.4,4837.5 h60
  text "9.00mil" at 8720.16,4837.5 h60
  text "4.2" at 9370,4837.5 h60
  text "4" at 6520.74,4717.5 h60
  text "Bottom Layer" at 6930.65,4717.5 h60
  text "1.40mil" at 8720.16,4717.5 h60
  text "Bottom Solder" at 6930.65,4597.5 h60
  text "Solder Resist" at 7860.4,4597.5 h60
  text "0.40mil" at 8720.16,4597.5 h60
  text "3.5" at 9370,4597.5 h60
  text "Bottom Overlay" at 6930.65,4477.5 h60
  text ".Layer_Name" at 577,-858.49 h60
M13 Component Bodies Top:
  text ".Layer_Name" at 577,-858.49 h60
M14 Component Bodies Bottom:
  text ".Layer_Name" at 577,-858.49 h60
M15 Courtyards Top:
  text ".Layer_Name" at 577,-858.49 h60
M16 Courtyards Bottom:
  text ".Layer_Name" at 577,-858.49 h60
Drill Drawing:
  circle w10: c5363.72,3401.64 r16.58
  circle w10: c5363.72,3401.64 r27.63
  circle w10: c5363.72,3153 r27.63
  lines w10: 5336.09,2268.95 5349.9,2268.95 5349.9,2255.14 5377.53,2255.14 5377.53,2268.95 5391.34,2268.95 5391.34,2296.58 5377.53,2296.58 5377.53,2310.39 5349.9,2310.39 5349.9,2296.58 5336.09,2296.58 5336.09,2268.95 ; 5336.09,2434.71 5391.34,2434.71 5363.72,2379.46 5336.09,2434.71 ; 5336.09,2517.59 5349.9,2517.59 5363.72,2503.78 5377.53,2517.59 5391.34,2517.59 5377.53,2531.4 5391.34,2545.22 5377.53,2545.22 5363.72,2559.03 5349.9,2545.22 5336.09,2545.22 5349.9,2531.4 5336.09,2517.59 ; 5336.09,2655.72 5363.72,2628.1 5391.34,2655.72 5363.72,2683.35 5336.09,2655.72 ; 5336.09,2766.23 5349.9,2766.23 5363.72,2752.42 5377.53,2766.23 5391.34,2766.23 5377.53,2780.04 5391.34,2793.86 5377.53,2793.86 5363.72,2807.67 5349.9,2793.86 5336.09,2793.86 5349.9,2780.04 5336.09,2766.23 ; 5336.09,2876.74 5363.72,2890.55 5391.34,2876.74 5377.53,2904.36 5391.34,2931.99 5363.72,2918.18 5336.09,2931.99 5349.9,2904.36 5336.09,2876.74 ; 5336.09,3056.31 5391.34,3056.31 5363.72,3001.06 5336.09,3056.31 ; 5336.09,3249.7 5336.09,3263.51 5349.9,3277.32 5336.09,3291.14 5336.09,3304.95 5349.9,3304.95 5363.72,3291.14 5377.53,3304.95 5391.34,3304.95 5391.34,3291.14 5377.53,3277.32 5391.34,3263.51 5391.34,3249.7 5377.53,3249.7 5363.72,3263.51 5349.9,3249.7 5336.09,3249.7 ; 5336.09,3498.34 5391.34,3498.34 5391.34,3553.59 5336.09,3553.59 5336.09,3498.34 ; 5336.09,3622.66 5391.34,3622.66 5391.34,3677.91 5336.09,3677.91 5336.09,3622.66 ; 5347.14,2771.75 5355.43,2771.75 5363.72,2763.47 5372.01,2771.75 5380.29,2771.75 5372.01,2780.04 5380.29,2788.33 5372.01,2788.33 5363.72,2796.62 5355.43,2788.33 5347.14,2788.33 5355.43,2780.04 5347.14,2771.75 ; 5347.14,3045.26 5380.29,3045.26 5363.72,3012.11 5347.14,3045.26 ; 5347.14,3633.71 5380.29,3633.71 5380.29,3666.86 5347.14,3666.86 5347.14,3633.71
  lines w12: 5286,2217.84 8517.49,2217.84 ; 5286,3709.68 8517.49,3709.68 ; 5623.86,2093.52 5623.86,3834 ; 5955.86,2093.52 5955.86,3834 ; 6592.43,2093.52 6592.43,3834 ; 6851.57,2093.52 6851.57,3834 ; 7226.72,2093.52 7226.72,3834 ; 7951.05,2093.52 7951.05,3834 ; 5286,2093.52 8517.49,2093.52 8517.49,3834 5286,3834 5286,2093.52
  text "Symbol" at 5360.59,3746.98 h72
  text "Quantity" at 5661.16,3746.98 h72
  text "Finished Hole Size" at 5993.16,3746.98 h72
  text "Plated" at 6629.72,3746.98 h72
  text "Hole Type" at 6888.86,3746.98 h72
  text "Drill Layer Pair" at 7264.02,3746.98 h72
  text "Hole Tolerance" at 7988.35,3746.98 h72
  text "2" at 5661.16,3622.66 h60
  text "40.00mil (1.016mm)" at 5993.16,3622.66 h60
  text "NPTH" at 6629.72,3622.66 h60
  text "Round" at 6888.86,3622.66 h60
  text "Top Layer - Bottom Layer" at 7264.02,3622.66 h60
  text "2" at 5661.16,3498.34 h60
  text "173.23mil (4.400mm)" at 5993.16,3498.34 h60
  text "NPTH" at 6629.72,3498.34 h60
  text "Round" at 6888.86,3498.34 h60
  text "Top Layer - Bottom Layer" at 7264.02,3498.34 h60
  text "19" at 5661.16,3374.02 h60
  text "7.87mil (0.200mm)" at 5993.16,3374.02 h60
  text "PTH" at 6629.72,3374.02 h60
  text "Round" at 6888.86,3374.02 h60
  text "Top Layer - Bottom Layer" at 7264.02,3374.02 h60
  text "191" at 5661.16,3249.7 h60
  text "16.00mil (0.406mm)" at 5993.16,3249.7 h60
  text "PTH" at 6629.72,3249.7 h60
  text "Round" at 6888.86,3249.7 h60
  text "Top Layer - Bottom Layer" at 7264.02,3249.7 h60
  text "4" at 5661.16,3125.38 h60
  text "18.00mil (0.457mm)" at 5993.16,3125.38 h60
  text "PTH" at 6629.72,3125.38 h60
  text "Round" at 6888.86,3125.38 h60
  text "Top Layer - Bottom Layer" at 7264.02,3125.38 h60
  text "15" at 5661.16,3001.06 h60
  text "28.00mil (0.711mm)" at 5993.16,3001.06 h60
  text "PTH" at 6629.72,3001.06 h60
  text "Round" at 6888.86,3001.06 h60
  text "Top Layer - Bottom Layer" at 7264.02,3001.06 h60
  text "54" at 5661.16,2876.74 h60
  text "40.00mil (1.016mm)" at 5993.16,2876.74 h60
  text "PTH" at 6629.72,2876.74 h60
  text "Round" at 6888.86,2876.74 h60
  text "Top Layer - Bottom Layer" at 7264.02,2876.74 h60
  text "9" at 5661.16,2752.42 h60
  text "43.31mil (1.100mm)" at 5993.16,2752.42 h60
  text "PTH" at 6629.72,2752.42 h60
  text "Round" at 6888.86,2752.42 h60
  text "Top Layer - Bottom Layer" at 7264.02,2752.42 h60
  text "6" at 5661.16,2628.1 h60
  text "50.00mil (1.270mm)" at 5993.16,2628.1 h60
  text "PTH" at 6629.72,2628.1 h60
  text "Round" at 6888.86,2628.1 h60
  text "Top Layer - Bottom Layer" at 7264.02,2628.1 h60
  text "2" at 5661.16,2503.78 h60
  text "59.06mil (1.500mm)" at 5993.16,2503.78 h60
  text "PTH" at 6629.72,2503.78 h60
  text "Round" at 6888.86,2503.78 h60
  text "Top Layer - Bottom Layer" at 7264.02,2503.78 h60
  text "8" at 5661.16,2379.46 h60
  text "66.93mil (1.700mm)" at 5993.16,2379.46 h60
  text "PTH" at 6629.72,2379.46 h60
  text "Round" at 6888.86,2379.46 h60
  text "Top Layer - Bottom Layer" at 7264.02,2379.46 h60
  text "2" at 5661.16,2255.14 h60
  text "80.71mil (2.050mm)" at 5993.16,2255.14 h60
  text "PTH" at 6629.72,2255.14 h60
  text "Round" at 6888.86,2255.14 h60
  text "Top Layer - Bottom Layer" at 7264.02,2255.14 h60
  text "314 Total" at 5661.16,2130.82 h60
  text ".Layer_Name" at 577,-858.49 h60
M17 Embedded Cavity:
  text ".Layer_Name" at 577,-858.49 h60
M18 Embedded Assembly:
  text ".Layer_Name" at 577,-858.49 h60
M19 Embedded Keepout:
  text ".Layer_Name" at 577,-858.49 h60

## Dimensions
0,0 to -10,2800 on M2 Board Dimensions
0,0 to 4800,0 on M2 Board Dimensions
0,-400 to 1000,-400 on M2 Board Dimensions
